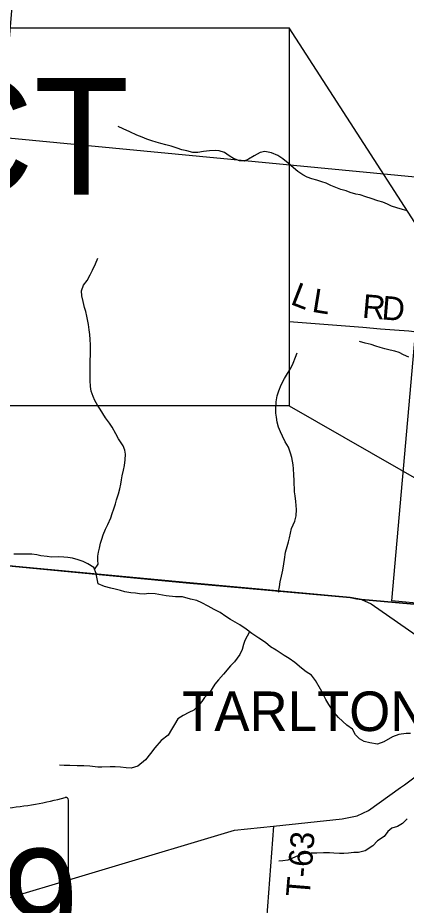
# Model space of a CAD drawing. Extents: x 0 to 42.5, y 0 to 22.
# Drawn here: x 6.449 to 6.916, y 18.353 to 19.417 of the extents above; entities that cross this region are included whole.
import ezdxf

# ---------------------------------------------------------------- set-up
doc = ezdxf.new("R2010")
doc.units = 0
for name, color, linetype in [('Default', 7, 'Continuous'), ('GM_X_Corporation_Text', 7, 'Continuous'), ('GM_X_County_Road', 7, 'Continuous'), ('GM_X_Interchange_Ramps', 7, 'Continuous'), ('GM_X_Minor_River', 7, 'Continuous'), ('GM_X_Section', 7, 'Continuous'), ('GM_X_State_Route', 7, 'Continuous'), ('GM_X_State_Shield', 7, 'Continuous'), ('GM_X_Township', 7, 'Continuous'), ('GM_X_Township_Road', 7, 'Continuous'), ('GM_X_Township_Road_Text', 7, 'Continuous'), ('SH_Cut_Line', 7, 'Continuous'), ('SH_Text', 7, 'Continuous')]:
    doc.layers.add(name, color=color, linetype=linetype)

msp = doc.modelspace()

# ---------------------------------------------------------------- linework, layer by layer
at = {"layer": 'Default'}
msp.add_lwpolyline([(6.7752, 18.9515), (7.24, 18.6854), (6.7752, 19.405)], close=True, dxfattribs=at)
at = {"layer": 'GM_X_County_Road'}
for points in [[(6.4255, 18.7608), (6.6516, 18.7394), (6.8484, 18.7216), (6.856, 18.7203), (6.862, 18.7192)], [(6.862, 18.7192), (6.8735, 18.7141), (6.9366, 18.6703), (6.9394, 18.6684)]]:
    msp.add_lwpolyline(points, dxfattribs=at)
at = {"layer": 'GM_X_Interchange_Ramps'}
msp.add_lwpolyline([(6.4254, 18.761), (6.6515, 18.7397), (6.8483, 18.7218), (6.8619, 18.7195), (7.165, 18.6924), (7.2398, 18.6857), (7.2611, 18.6839), (7.3333, 18.6776), (7.3503, 18.6764), (7.4023, 18.6719), (7.4511, 18.6665), (7.5067, 18.662), (7.569, 18.6562), (7.6874, 18.6472), (7.929, 18.6269)], dxfattribs=at)
at = {"layer": 'GM_X_Minor_River'}
for points in [[(6.9165, 19.1856), (6.9112, 19.1872), (6.9042, 19.1891), (6.898, 19.1911), (6.8931, 19.1933), (6.8873, 19.1956), (6.8816, 19.1974), (6.8735, 19.2003), (6.867, 19.2021), (6.8601, 19.2045), (6.8551, 19.2055), (6.8483, 19.2074), (6.8434, 19.2092), (6.8372, 19.211), (6.8312, 19.2133), (6.8249, 19.2159), (6.8195, 19.2184), (6.8142, 19.2202), (6.8083, 19.2221), (6.8023, 19.2239), (6.7968, 19.2259), (6.7915, 19.2284), (6.7855, 19.2324), (6.7801, 19.2371), (6.774, 19.2426), (6.7673, 19.2477), (6.7615, 19.2517), (6.7539, 19.2548), (6.746, 19.2564), (6.7401, 19.2552), (6.7332, 19.2513), (6.7261, 19.2472), (6.721, 19.2451), (6.7153, 19.2452), (6.7083, 19.2483), (6.7031, 19.2514), (6.6974, 19.2553), (6.6912, 19.2574), (6.6863, 19.2577), (6.6794, 19.2574), (6.6722, 19.2565), (6.6654, 19.2552), (6.6595, 19.2553), (6.6521, 19.2573), (6.6463, 19.2585), (6.6408, 19.2604), (6.6334, 19.2628), (6.6272, 19.2646), (6.6211, 19.266), (6.6155, 19.2677), (6.6104, 19.2695), (6.6043, 19.2715), (6.5985, 19.2736), (6.5924, 19.276), (6.5838, 19.2801), (6.5758, 19.2838), (6.57, 19.2865)], [(6.5415, 18.7555), (6.5461, 18.7619), (6.5457, 18.7667), (6.5456, 18.7714), (6.5462, 18.7762), (6.5474, 18.7811), (6.5488, 18.7868), (6.5502, 18.7919), (6.552, 18.797), (6.5547, 18.8036), (6.5574, 18.8093), (6.5611, 18.8174), (6.5627, 18.8225), (6.5648, 18.8282), (6.5666, 18.8339), (6.568, 18.839), (6.5702, 18.8462), (6.5718, 18.8521), (6.573, 18.8578), (6.574, 18.8627), (6.5748, 18.8676), (6.5762, 18.8743), (6.5774, 18.8801), (6.5782, 18.8868), (6.5787, 18.8938), (6.5778, 18.8986), (6.5758, 18.9037), (6.5702, 18.9121), (6.567, 18.9179), (6.5626, 18.9259), (6.5594, 18.9309), (6.5549, 18.937), (6.5482, 18.9474), (6.5452, 18.9525), (6.5421, 18.9579), (6.5399, 18.9626), (6.5377, 18.9691), (6.5368, 18.9747), (6.5365, 18.9821), (6.5364, 18.9887), (6.5364, 18.9952), (6.5363, 19.0001), (6.5364, 19.0066), (6.5366, 19.0121), (6.5367, 19.0185), (6.5366, 19.0246), (6.5363, 19.0313), (6.5358, 19.0372), (6.5351, 19.0427), (6.5342, 19.0492), (6.5325, 19.0591), (6.5312, 19.0648), (6.5297, 19.0695), (6.5279, 19.0766), (6.5263, 19.0833), (6.5258, 19.0895), (6.5285, 19.0962), (6.5328, 19.102), (6.5363, 19.1086), (6.5392, 19.1143), (6.5427, 19.1217), (6.5454, 19.1285)], [(6.9187, 19.0098), (6.9124, 19.0129), (6.907, 19.0154), (6.9019, 19.017), (6.8962, 19.0182), (6.8899, 19.0198), (6.8843, 19.0216), (6.879, 19.0233), (6.8735, 19.0251), (6.8661, 19.0269), (6.8593, 19.0287)], [(6.7626, 18.7279), (6.7624, 18.729), (6.7636, 18.7346), (6.7644, 18.7407), (6.766, 18.7475), (6.7676, 18.7546), (6.7688, 18.7621), (6.7695, 18.7673), (6.7707, 18.776), (6.7725, 18.783), (6.7741, 18.7885), (6.7753, 18.7932), (6.7765, 18.7989), (6.778, 18.8046), (6.7819, 18.8133), (6.7835, 18.8197), (6.784, 18.8272), (6.7832, 18.837), (6.7823, 18.8435), (6.7816, 18.8485), (6.781, 18.8621), (6.7807, 18.8688), (6.7804, 18.876), (6.7799, 18.881), (6.7783, 18.8897), (6.7768, 18.8949), (6.7741, 18.9019), (6.7703, 18.9086), (6.7672, 18.9153), (6.7648, 18.9203), (6.7624, 18.926), (6.7606, 18.9321), (6.7597, 18.938), (6.7592, 18.9428), (6.759, 18.9477), (6.7593, 18.9563), (6.7606, 18.9637), (6.7625, 18.9697), (6.7653, 18.9769), (6.7695, 18.9843), (6.7732, 18.9903), (6.7771, 18.9967), (6.7798, 19.0028), (6.7827, 19.01), (6.7847, 19.0153)], [(6.5443, 18.7462), (6.5435, 18.7507), (6.5407, 18.7576), (6.5334, 18.7622), (6.5281, 18.7648), (6.522, 18.7669), (6.5152, 18.7691), (6.5094, 18.7699), (6.5046, 18.7702), (6.498, 18.7706), (6.49, 18.7703), (6.4849, 18.7708), (6.4773, 18.7718), (6.4724, 18.7728), (6.4662, 18.7736), (6.4605, 18.7739), (6.455, 18.7739), (6.4503, 18.7738), (6.4446, 18.7739)], [(6.9205, 18.5587), (6.9156, 18.5588), (6.9066, 18.5573), (6.8991, 18.5547), (6.8886, 18.5485), (6.8809, 18.5457), (6.8719, 18.5475), (6.865, 18.5491), (6.8593, 18.5521), (6.8547, 18.5569), (6.8511, 18.5638), (6.8444, 18.5688), (6.8341, 18.578), (6.8295, 18.5833), (6.8257, 18.5885), (6.8227, 18.5934), (6.8192, 18.5994), (6.8168, 18.6041), (6.8128, 18.6119), (6.8067, 18.6222), (6.8017, 18.6287), (6.7956, 18.6328), (6.7899, 18.637), (6.7818, 18.6437), (6.7752, 18.6485), (6.7692, 18.6523), (6.7595, 18.6587), (6.7528, 18.6627), (6.7465, 18.6679), (6.7385, 18.6729), (6.7303, 18.6786), (6.7234, 18.6838), (6.7158, 18.6888), (6.7045, 18.6955), (6.699, 18.6988), (6.6921, 18.7038), (6.685, 18.7073), (6.6777, 18.7113), (6.6701, 18.7155), (6.6644, 18.7181), (6.6567, 18.7198), (6.6472, 18.7227), (6.6388, 18.7224), (6.6273, 18.7236), (6.6141, 18.7262), (6.6066, 18.7266), (6.6011, 18.7259), (6.5955, 18.7262), (6.5906, 18.7268), (6.585, 18.7272), (6.5781, 18.7284), (6.5728, 18.7303), (6.5665, 18.7317), (6.5613, 18.7331), (6.5535, 18.735), (6.5458, 18.7383), (6.5444, 18.746)], [(6.7276, 18.6807), (6.7218, 18.6703), (6.7203, 18.6652), (6.7188, 18.6594), (6.7157, 18.6533), (6.7094, 18.6446), (6.7048, 18.6397), (6.6961, 18.6299), (6.6904, 18.6231), (6.686, 18.6178), (6.6796, 18.6074), (6.6733, 18.6019), (6.6702, 18.597), (6.6656, 18.5914), (6.6607, 18.5865), (6.6545, 18.5838), (6.6478, 18.5803), (6.6413, 18.5761), (6.6373, 18.5695), (6.634, 18.5635), (6.63, 18.5567), (6.6214, 18.5503), (6.6139, 18.5414), (6.6085, 18.5346), (6.6026, 18.5272), (6.5936, 18.5197), (6.5855, 18.5173), (6.5794, 18.5175), (6.5727, 18.5185), (6.5662, 18.5186), (6.5603, 18.5186), (6.5503, 18.5183), (6.5454, 18.5185), (6.5358, 18.5194), (6.5287, 18.5198), (6.5209, 18.52), (6.5121, 18.5203), (6.5052, 18.5203), (6.4997, 18.5209)], [(6.9165, 18.4564), (6.9111, 18.4507), (6.905, 18.4473), (6.8981, 18.4451), (6.8933, 18.4412), (6.8889, 18.4353), (6.8812, 18.43), (6.8755, 18.424), (6.8663, 18.418), (6.8581, 18.4158), (6.8525, 18.4158), (6.8464, 18.4153), (6.8405, 18.4146), (6.8353, 18.4148), (6.8288, 18.4152), (6.8236, 18.4155), (6.8162, 18.4155), (6.8083, 18.4152), (6.8014, 18.415), (6.7953, 18.4147), (6.7903, 18.414), (6.7856, 18.4121), (6.7789, 18.4093), (6.7735, 18.4069), (6.7676, 18.4058), (6.7626, 18.4055)]]:
    msp.add_lwpolyline(points, dxfattribs=at)
at = {"layer": 'GM_X_Section'}
for points in [[(6.4717, 19.7723), (6.9869, 19.728), (6.9432, 19.2241), (6.4295, 19.2734)], [(6.9432, 19.2241), (7.4474, 19.1773), (7.4064, 18.6718), (6.9401, 18.7138), (6.8981, 18.7177)]]:
    msp.add_lwpolyline(points, close=True, dxfattribs=at)
at = {"layer": 'GM_X_State_Route'}
for points in [[(6.9134, 18.4973), (6.9264, 18.5066), (7.0274, 18.6073), (7.0403, 18.6173), (7.0499, 18.6203), (7.0736, 18.6235), (7.087, 18.6255)], [(5.3632, 17.7531), (5.4906, 17.84), (5.892, 18.1007), (6.1024, 18.2447), (6.1261, 18.2588), (6.1733, 18.2837), (6.3996, 18.3499), (6.7096, 18.4427), (6.7563, 18.4476), (6.8385, 18.4563), (6.8567, 18.4598), (6.8701, 18.4664), (6.9087, 18.494), (6.9134, 18.4973)]]:
    msp.add_lwpolyline(points, dxfattribs=at)
at = {"layer": 'GM_X_State_Shield'}
for p, q in [((6.5103, 18.381), (6.5103, 18.4789)), ((6.5102, 18.381), (6.5103, 18.381))]:
    msp.add_line(p, q, dxfattribs=at)
for centre, major_axis, start_param, end_param in [((6.4005, 18.7294), (0.3269, 0), 4.814394, 5.042369), ((6.5068, 18.4793), (0.00343, 0), 6.141152, 7.989035), ((6.5066, 18.3806), (0.00367, 0), 5.05454, 6.418171), ((6.5095, 18.3738), (0.00531, 0), 1.883978, 3.671073), ((6.4757, 18.3614), (0.0319, 0), 5.934695, 6.695948)]:
    msp.add_ellipse(centre, major_axis=major_axis, ratio=0.8, start_param=start_param, end_param=end_param, dxfattribs=at)
at = {"layer": 'GM_X_Township'}
msp.add_lwpolyline([(6.4254, 18.761), (6.6515, 18.7397), (6.8483, 18.7218), (6.8619, 18.7195), (7.165, 18.6924), (7.2398, 18.6857), (7.2611, 18.6839), (7.3333, 18.6776), (7.3503, 18.6764), (7.4023, 18.6719), (7.4511, 18.6665), (7.5067, 18.662), (7.569, 18.6562), (7.6874, 18.6472), (7.929, 18.6269)], dxfattribs=at)
at = {"layer": 'GM_X_Township_Road'}
for points in [[(7.069, 19.0163), (7.0624, 19.0165), (7.0341, 19.0173), (7.0252, 19.0181), (7.0208, 19.0189), (6.9952, 19.025), (6.9745, 19.0297), (6.9528, 19.0341), (6.9378, 19.0386), (6.9278, 19.0398), (6.9185, 19.0411), (6.9015, 19.0425), (6.8848, 19.0435), (6.8635, 19.0457), (6.7752, 19.0522)], [(6.7563, 18.4476), (6.7396, 18.2236), (6.741, 18.2194), (6.7456, 18.2169), (6.8888, 18.2062), (6.8922, 18.2054), (6.8944, 18.1978), (6.8876, 18.0912)]]:
    msp.add_lwpolyline(points, dxfattribs=at)
at = {"layer": 'SH_Cut_Line'}
for points in [[(7.929, 18.6269), (7.6874, 18.6472), (7.569, 18.6562), (7.5067, 18.662), (7.4511, 18.6665), (7.4023, 18.6719), (7.3503, 18.6764), (7.3333, 18.6776), (7.2611, 18.6839), (7.2398, 18.6857), (7.165, 18.6924), (6.8619, 18.7195), (6.8483, 18.7218), (6.6515, 18.7397), (6.4254, 18.761)], [(6.4254, 18.761), (6.6515, 18.7397), (6.8483, 18.7218), (6.8619, 18.7195), (7.165, 18.6924), (7.2398, 18.6857), (7.2611, 18.6839), (7.3333, 18.6776), (7.3503, 18.6764), (7.4023, 18.6719), (7.4511, 18.6665), (7.5067, 18.662), (7.569, 18.6562), (7.6874, 18.6472), (7.929, 18.6269)]]:
    msp.add_lwpolyline(points, dxfattribs=at)
at = {"layer": 'SH_Text'}
msp.add_lwpolyline([(5.0697, 19.405), (6.7752, 19.405), (6.7752, 18.9515), (5.0697, 18.9515)], close=True, dxfattribs=at)

# ---------------------------------------------------------------- texts
at = {"layer": 'GM_X_Corporation_Text'}
for p in [(6.6466, 18.5617), (6.6466, 18.5616)]:
    msp.add_text('TARLTON', height=0.04735, rotation=0, dxfattribs=at).set_placement(p)
at = {"layer": 'GM_X_State_Shield'}
msp.add_text('159', height=0.1233, dxfattribs=at).set_placement((6.2473, 18.2971))
at = {"layer": 'GM_X_Township_Road_Text'}
for s, height, rotation, p in [('L', 0.0284, 338.7545, (6.7754, 19.0739)), ('L', 0.0284, 350.8147, (6.8014, 19.0645)), ('R', 0.0284, 355.0116, (6.862, 19.0573)), ('D', 0.0284, 355.3237, (6.8854, 19.0553)), ('T-63', 0.02841, 85.3834, (6.7995, 18.3621))]:
    msp.add_text(s, height=height, rotation=rotation, dxfattribs=at).set_placement(p)
at = {"layer": 'SH_Text'}
msp.add_text('END PROJECT', height=0.14, dxfattribs=at).set_placement((5.262, 19.2046))

doc.saveas('drawing.dxf')
